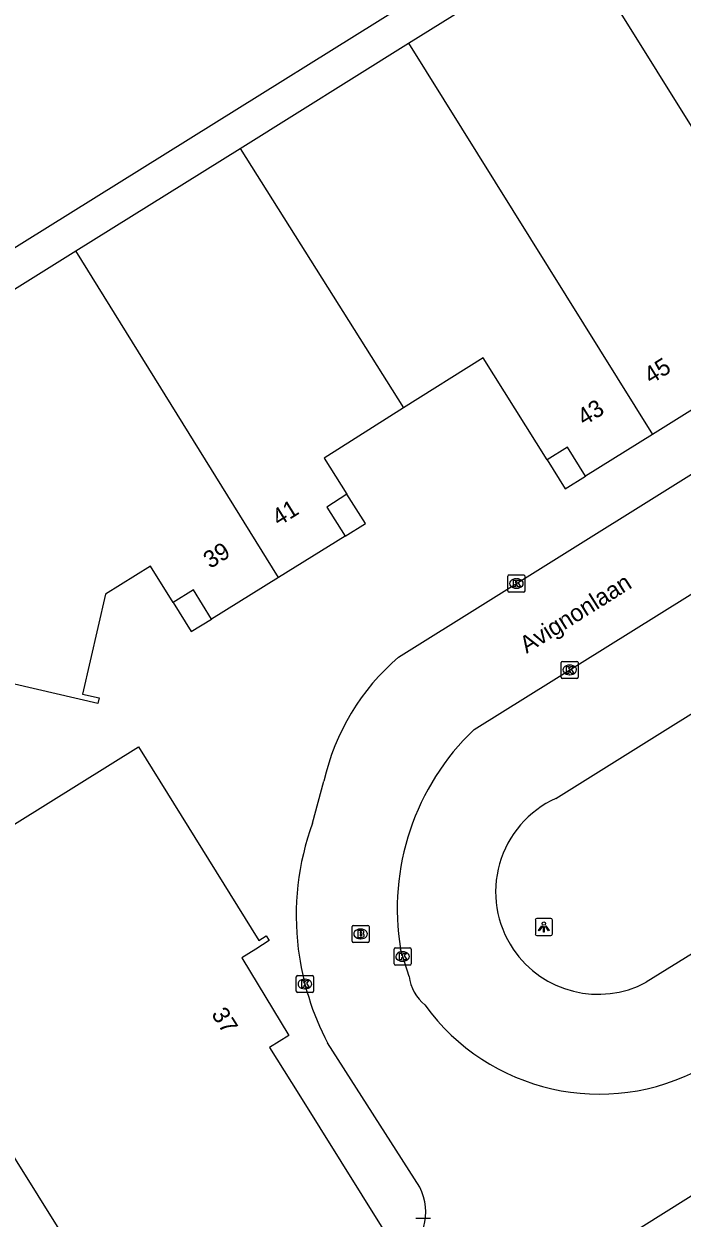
# Model space of a CAD drawing. Extents: x 158461 to 159795, y 387220 to 388672.
# Drawn here: x 158755 to 158793.6, y 387484.3 to 387554.1 of the extents above; entities that cross this region are included whole.
import ezdxf

# ---------------------------------------------------------------- set-up
doc = ezdxf.new("R2010")
doc.units = 0
for name, color, linetype in [('IMGEO_Brandkraan', 7, 'Continuous'), ('IMGEO_Kolk', 7, 'Continuous'), ('IMGEO_Lichtpunt', 7, 'Continuous'), ('IMGEO_Openbare_ruimte_label', 7, 'Continuous'), ('IMGEO_Pand', 7, 'Continuous'), ('IMGEO_Pand_nummerreeks', 7, 'Continuous'), ('IMGEO_Pand_overbouw', 7, 'Continuous'), ('IMGEO_Rijbaan_lokaal_open', 7, 'Continuous'), ('IMGEO_Voetpad_open', 7, 'Continuous')]:
    doc.layers.add(name, color=color, linetype=linetype)

msp = doc.modelspace()

# ---------------------------------------------------------------- linework, layer by layer
at = {"layer": 'IMGEO_Brandkraan'}
for p, q in [((158774.244, 387500.459), (158774.244, 387501.311)), ((158774.319, 387501.385), (158775.171, 387501.385)), ((158774.732, 387501.165), (158774.757, 387501.165)), ((158775.245, 387501.311), (158775.245, 387500.459)), ((158775.171, 387500.385), (158774.319, 387500.385)), ((158774.755, 387500.605), (158774.73, 387500.605))]:
    msp.add_line(p, q, dxfattribs=at)
for points in [[(158774.244, 387500.459), (158774.244, 387501.311)], [(158774.319, 387501.385), (158775.171, 387501.385)], [(158774.592, 387501.085), (158774.592, 387500.685), (158774.805, 387500.685)], [(158774.823, 387501.085), (158774.592, 387501.085)], [(158774.771, 387501.004), (158774.717, 387501.004), (158774.717, 387500.928)], [(158774.717, 387500.928), (158774.77, 387500.928)], [(158775.245, 387501.311), (158775.245, 387500.459)], [(158775.171, 387500.385), (158774.319, 387500.385)], [(158774.779, 387500.852), (158774.717, 387500.852), (158774.717, 387500.771)], [(158774.717, 387500.771), (158774.779, 387500.771)]]:
    msp.add_lwpolyline(points, dxfattribs=at)
for centre, radius, start, end in [((158774.321, 387501.309), 0.0765, 91.55205, 178.44795), ((158774.321, 387501.309), 0.0765, 91.55205, 178.44795), ((158774.772, 387500.966), 0.0379, 267.82845, 90.93552), ((158774.827, 387500.94), 0.145, 59.4692, 91.53667), ((158774.852, 387500.987), 0.0922, 285.51372, 58.15012), ((158774.857, 387500.795), 0.105, 301.31148, 78.98903), ((158775.169, 387501.309), 0.0765, 1.55205, 88.44795), ((158775.169, 387501.309), 0.0765, 1.55205, 88.44795), ((158774.321, 387500.461), 0.0765, 181.55205, 268.44795), ((158774.321, 387500.461), 0.0765, 181.55205, 268.44795), ((158774.78, 387500.811), 0.0404, 269.87594, 90.50774), ((158774.811, 387500.936), 0.251, 268.66757, 293.53466), ((158775.169, 387500.461), 0.0765, 271.55205, 358.44795), ((158775.169, 387500.461), 0.0765, 271.55205, 358.44795)]:
    msp.add_arc(centre, radius, start, end, dxfattribs=at)
for centre, major_axis, ratio, start_param, end_param in [((158774.731, 387500.885), (-0.387, 0.002), 0.722429, 4.712389, 7.853982), ((158774.756, 387500.885), (-0.39, 0.002), 0.717154, 1.570796, 4.712389)]:
    msp.add_ellipse(centre, major_axis=major_axis, ratio=ratio, start_param=start_param, end_param=end_param, dxfattribs=at)
at = {"layer": 'IMGEO_Kolk'}
for p, q in [((158783.441, 387521.89), (158784.293, 387521.89)), ((158783.366, 387520.964), (158783.366, 387521.816)), ((158783.854, 387521.67), (158783.879, 387521.67)), ((158784.367, 387521.816), (158784.367, 387520.964)), ((158784.293, 387520.89), (158783.441, 387520.89)), ((158783.877, 387521.11), (158783.852, 387521.11)), ((158786.483, 387515.907), (158786.483, 387516.759)), ((158786.558, 387516.833), (158787.41, 387516.833)), ((158786.971, 387516.613), (158786.996, 387516.613)), ((158787.484, 387516.759), (158787.484, 387515.907)), ((158787.41, 387515.833), (158786.558, 387515.833)), ((158786.994, 387516.053), (158786.969, 387516.053)), ((158776.704, 387499.139), (158776.704, 387499.991)), ((158776.779, 387500.065), (158777.631, 387500.065)), ((158777.192, 387499.845), (158777.217, 387499.845)), ((158777.705, 387499.991), (158777.705, 387499.139)), ((158777.631, 387499.065), (158776.779, 387499.065)), ((158777.215, 387499.285), (158777.19, 387499.285)), ((158770.982, 387497.528), (158770.982, 387498.38)), ((158771.057, 387498.454), (158771.909, 387498.454)), ((158771.47, 387498.234), (158771.495, 387498.234)), ((158771.983, 387498.38), (158771.983, 387497.528)), ((158771.909, 387497.454), (158771.057, 387497.454)), ((158771.493, 387497.674), (158771.468, 387497.674)), ((158777.977, 387484.255), (158778.829, 387484.255))]:
    msp.add_line(p, q, dxfattribs=at)
for points in [[(158783.441, 387521.89), (158784.293, 387521.89)], [(158783.366, 387520.964), (158783.366, 387521.816)], [(158783.687, 387521.59), (158783.81, 387521.59), (158783.81, 387521.439), (158783.94, 387521.59), (158784.104, 387521.59), (158783.958, 387521.439), (158784.111, 387521.19), (158783.959, 387521.19), (158783.874, 387521.354), (158783.81, 387521.287), (158783.81, 387521.19), (158783.687, 387521.19), (158783.687, 387521.59)], [(158784.367, 387521.816), (158784.367, 387520.964)], [(158784.293, 387520.89), (158783.441, 387520.89)], [(158786.483, 387515.907), (158786.483, 387516.759)], [(158786.558, 387516.833), (158787.41, 387516.833)], [(158786.804, 387516.533), (158786.927, 387516.533), (158786.927, 387516.382), (158787.057, 387516.533), (158787.221, 387516.533), (158787.075, 387516.382), (158787.228, 387516.133), (158787.076, 387516.133), (158786.991, 387516.297), (158786.927, 387516.23), (158786.927, 387516.133), (158786.804, 387516.133), (158786.804, 387516.533)], [(158787.484, 387516.759), (158787.484, 387515.907)], [(158787.41, 387515.833), (158786.558, 387515.833)], [(158776.704, 387499.139), (158776.704, 387499.991)], [(158776.779, 387500.065), (158777.631, 387500.065)], [(158777.025, 387499.765), (158777.148, 387499.765), (158777.148, 387499.614), (158777.278, 387499.765), (158777.442, 387499.765), (158777.296, 387499.614), (158777.449, 387499.365), (158777.297, 387499.365), (158777.212, 387499.529), (158777.148, 387499.462), (158777.148, 387499.365), (158777.025, 387499.365), (158777.025, 387499.765)], [(158777.705, 387499.991), (158777.705, 387499.139)], [(158777.631, 387499.065), (158776.779, 387499.065)], [(158770.982, 387497.528), (158770.982, 387498.38)], [(158771.057, 387498.454), (158771.909, 387498.454)], [(158771.303, 387498.154), (158771.426, 387498.154), (158771.426, 387498.003), (158771.556, 387498.154), (158771.72, 387498.154), (158771.574, 387498.003), (158771.727, 387497.754), (158771.575, 387497.754), (158771.49, 387497.918), (158771.426, 387497.851), (158771.426, 387497.754), (158771.303, 387497.754), (158771.303, 387498.154)], [(158771.983, 387498.38), (158771.983, 387497.528)], [(158771.909, 387497.454), (158771.057, 387497.454)], [(158777.977, 387484.255), (158778.829, 387484.255)]]:
    msp.add_lwpolyline(points, dxfattribs=at)
for centre, start, end in [((158783.443, 387521.814), 91.55205, 178.44795), ((158783.443, 387521.814), 91.55205, 178.44795), ((158784.291, 387521.814), 1.55205, 88.44795), ((158784.291, 387521.814), 1.55205, 88.44795), ((158783.443, 387520.966), 181.55205, 268.44795), ((158783.443, 387520.966), 181.55205, 268.44795), ((158784.291, 387520.966), 271.55205, 358.44795), ((158784.291, 387520.966), 271.55205, 358.44795), ((158786.56, 387516.757), 91.55205, 178.44795), ((158786.56, 387516.757), 91.55205, 178.44795), ((158787.408, 387516.757), 1.55205, 88.44795), ((158787.408, 387516.757), 1.55205, 88.44795), ((158786.56, 387515.909), 181.55205, 268.44795), ((158786.56, 387515.909), 181.55205, 268.44795), ((158787.408, 387515.909), 271.55205, 358.44795), ((158787.408, 387515.909), 271.55205, 358.44795), ((158776.781, 387499.989), 91.55205, 178.44795), ((158776.781, 387499.989), 91.55205, 178.44795), ((158777.629, 387499.989), 1.55205, 88.44795), ((158777.629, 387499.989), 1.55205, 88.44795), ((158776.781, 387499.141), 181.55205, 268.44795), ((158776.781, 387499.141), 181.55205, 268.44795), ((158777.629, 387499.141), 271.55205, 358.44795), ((158777.629, 387499.141), 271.55205, 358.44795), ((158771.059, 387498.378), 91.55205, 178.44795), ((158771.059, 387498.378), 91.55205, 178.44795), ((158771.907, 387498.378), 1.55205, 88.44795), ((158771.907, 387498.378), 1.55205, 88.44795), ((158771.059, 387497.53), 181.55205, 268.44795), ((158771.059, 387497.53), 181.55205, 268.44795), ((158771.907, 387497.53), 271.55205, 358.44795), ((158771.907, 387497.53), 271.55205, 358.44795)]:
    msp.add_arc(centre, 0.0765, start, end, dxfattribs=at)
for centre, major_axis, ratio, start_param, end_param in [((158783.853, 387521.39), (-0.387, 0.002), 0.722429, 4.712389, 7.853982), ((158783.878, 387521.39), (-0.39, 0.002), 0.717154, 1.570796, 4.712389), ((158786.97, 387516.333), (-0.387, 0.002), 0.722429, 4.712389, 7.853982), ((158786.995, 387516.333), (-0.39, 0.002), 0.717154, 1.570796, 4.712389), ((158777.191, 387499.565), (-0.387, 0.002), 0.722429, 4.712389, 7.853982), ((158777.216, 387499.565), (-0.39, 0.002), 0.717154, 1.570796, 4.712389), ((158771.469, 387497.954), (-0.387, 0.002), 0.722429, 4.712389, 7.853982), ((158771.494, 387497.954), (-0.39, 0.002), 0.717154, 1.570796, 4.712389)]:
    msp.add_ellipse(centre, major_axis=major_axis, ratio=ratio, start_param=start_param, end_param=end_param, dxfattribs=at)
at = {"layer": 'IMGEO_Lichtpunt'}
for p, q in [((158784.972, 387501.694), (158784.972, 387500.887)), ((158784.972, 387501.694), (158784.972, 387500.887)), ((158785.874, 387501.789), (158785.066, 387501.789)), ((158785.874, 387501.789), (158785.066, 387501.789)), ((158785.968, 387500.887), (158785.968, 387501.694)), ((158785.968, 387500.887), (158785.968, 387501.694)), ((158785.066, 387500.793), (158785.874, 387500.793)), ((158785.066, 387500.793), (158785.874, 387500.793))]:
    msp.add_line(p, q, dxfattribs=at)
for points in [[(158785.346, 387501.358), (158785.385, 387501.33), (158785.197, 387501.068), (158785.159, 387501.095), (158785.346, 387501.358)], [(158785.448, 387501.31), (158785.495, 387501.31), (158785.495, 387500.988), (158785.448, 387500.988), (158785.448, 387501.31)], [(158785.558, 387501.33), (158785.596, 387501.357), (158785.783, 387501.095), (158785.744, 387501.067), (158785.558, 387501.33)]]:
    msp.add_lwpolyline(points, dxfattribs=at)
msp.add_circle((158785.471, 387501.492), 0.0994, dxfattribs=at)
for centre, start, end in [((158785.066, 387501.694), 90, 180), ((158785.066, 387501.694), 90, 180), ((158785.874, 387501.694), 0, 90), ((158785.874, 387501.694), 0, 90), ((158785.066, 387500.887), 180, 270), ((158785.066, 387500.887), 180, 270), ((158785.874, 387500.887), 270, 0), ((158785.874, 387500.887), 270, 360)]:
    msp.add_arc(centre, 0.0946, start, end, dxfattribs=at)
at = {"layer": 'IMGEO_Pand'}
for points in [[(158749.516, 387537.927), (158738.745, 387555.234), (158752.109, 387563.618), (158751.515, 387564.592), (158754.723, 387566.608), (158755.385, 387565.623), (158781.522, 387581.924), (158792.348, 387564.63), (158749.516, 387537.927)], [(158777.539, 387553.003), (158787.28, 387559.084)], [(158787.28, 387559.084), (158799.185, 387539.994)], [(158767.688, 387546.853), (158777.539, 387553.003)], [(158777.539, 387553.003), (158791.82, 387530.113)], [(158758.083, 387540.857), (158767.688, 387546.853)], [(158767.688, 387546.853), (158777.262, 387531.665)], [(158769.933, 387521.744), (158766.012, 387519.313), (158764.959, 387521.013), (158763.77, 387520.276), (158762.452, 387522.401), (158759.809, 387520.763), (158758.473, 387514.922), (158759.435, 387514.695), (158759.368, 387514.374), (158754.495, 387515.491), (158746.001, 387517.438), (158746.247, 387518.511), (158738.888, 387520.198), (158736.998, 387519.014), (158736.302, 387518.578), (158732.469, 387524.866), (158758.083, 387540.857)], [(158769.933, 387521.744), (158758.083, 387540.857)], [(158799.185, 387539.994), (158794.518, 387537.084), (158795.836, 387534.971), (158794.663, 387534.233), (158795.723, 387532.548), (158791.82, 387530.113)], [(158791.82, 387530.113), (158787.912, 387527.674), (158786.85, 387529.37), (158785.663, 387528.627), (158781.924, 387534.604), (158777.262, 387531.665)], [(158777.262, 387531.665), (158772.609, 387528.733), (158773.939, 387526.623), (158772.769, 387525.853), (158773.843, 387524.168), (158769.933, 387521.744)], [(158762.308, 387475.257), (158746.866, 387500), (158745.717, 387501.841), (158761.741, 387511.827), (158768.797, 387500.506), (158769.226, 387500.781), (158769.4, 387500.503), (158768.61, 387500), (158767.794, 387499.481), (158770.54, 387494.943), (158769.42, 387494.242), (158771.128, 387491.512), (158776.056, 387483.637), (158762.408, 387475.096)]]:
    msp.add_lwpolyline(points, dxfattribs=at)
at = {"layer": 'IMGEO_Pand_overbouw'}
for points in [[(158786.85, 387529.37), (158785.663, 387528.627), (158786.723, 387526.932), (158787.912, 387527.674)], [(158773.939, 387526.623), (158772.769, 387525.853), (158773.843, 387524.168), (158775.025, 387524.901)], [(158764.959, 387521.013), (158763.77, 387520.276), (158764.824, 387518.576), (158766.012, 387519.313)]]:
    msp.add_lwpolyline(points, close=True, dxfattribs=at)
at = {"layer": 'IMGEO_Rijbaan_lokaal_open'}
for points in [[(158776.971, 387517.085), (158807.042, 387535.864), (158810.332, 387530.677)], [(158781.383, 387512.839), (158798.379, 387523.435)], [(158771.926, 387507.371), (158772.6, 387509.83)], [(158828.607, 387507.181), (158817.155, 387500), (158766.643, 387468.328), (158767.083, 387467.619), (158765.697, 387466.731)], [(158777.579, 387498.395), (158777.078, 387500)], [(158778.207, 387486.065), (158772.815, 387494.506)]]:
    msp.add_lwpolyline(points, dxfattribs=at)
for centre, radius, start, end in [((158785.686, 387506.89), 13.412, 130.52528, 167.33839), ((158791.372, 387502.348), 14.485, 133.59622, 189.33051), ((158786.944, 387501.943), 15.968, 160.12937, 186.99064), ((158786.955, 387501.952), 15.98, 187.0156, 207.77082), ((158780.154, 387498.743), 2.598, 187.69003, 230.80971), ((158788.716, 387504.103), 12.59, 215.85473, 298.67123), ((158775.429, 387484.619), 3.132, 300.80332, 27.50359)]:
    msp.add_arc(centre, radius, start, end, dxfattribs=at)
at = {"layer": 'IMGEO_Voetpad_open'}
for points in [[(158786.178, 387508.818), (158800.63, 387517.848)], [(158816.691, 387506.77), (158813.57, 387511.831), (158794.585, 387500), (158791.466, 387498.056)]]:
    msp.add_lwpolyline(points, dxfattribs=at)
for centre, radius, start, end in [((158788.649, 387503.351), 5.999, 114.31988, 213.96275), ((158788.648, 387503.35), 5.998, 213.96012, 298.02621)]:
    msp.add_arc(centre, radius, start, end, dxfattribs=at)

# ---------------------------------------------------------------- texts
at = {"layer": 'IMGEO_Openbare_ruimte_label'}
msp.add_text('Avignonlaan', height=1, rotation=32.08436, dxfattribs=at).set_placement((158784.463, 387517.269))
at = {"layer": 'IMGEO_Pand_nummerreeks'}
for s, rotation, p in [('45', 31.96383, (158791.736, 387533.03)), ('43', 31.96383, (158787.831, 387530.593)), ('41', 31.79775, (158769.951, 387524.72)), ('39', 31.79916, (158765.94, 387522.233)), ('37', 302.03287, (158765.982, 387496.194))]:
    msp.add_text(s, height=1, rotation=rotation, dxfattribs=at).set_placement(p)

doc.saveas('drawing.dxf')
